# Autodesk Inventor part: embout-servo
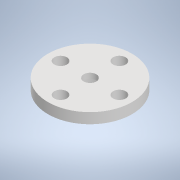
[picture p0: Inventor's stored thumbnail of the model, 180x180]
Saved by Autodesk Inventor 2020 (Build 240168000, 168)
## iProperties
Created: 2021-10
Part Number: embout-servo
Material: Générique
Document SubType Name: Modeling
Designer: bruno
Density: 26.3858 g/cm^3
Appearance: Par défaut
Mass: 20 g
Surface Area: 9.31691 cm^2
Volume: 0.757985 cm^3
Author: bruno
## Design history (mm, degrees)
sketch "Esquisse1"
  geometry: L1 (0, 0)-(2.5, 0); L2 (2, -4)-(0.5, -4); L3 (0, -3.5)-(0, -2.5); L4 (2.5, 0)-(5, 0); L5 (5, -1.5)-(5, -10); L6 (5, -10)-(2.5, -10); L7 (2.5, -10)-(2.5, -4.5); L8 (3.75, 0)-(0, 0); L9 (0, -1.5)-(0, -2.5); L10 (0, -2.5)-(3.75, -2.5); L11 (3.75, -2.5)-(3.75, -1.5); L12 (3.75, 0)-(5, 0); L13 (5, -1.5)-(3.75, -1.5); A1 r 0.5 centre (0.5, -3.5) between (0, -3.5) and (0.5, -4); A2 r 0.5 centre (2, -4.5) between (2.5, -4.5) and (2, -4)
  constraints: 26 end point, 6 parallel, 4 horizontal, 4 point on circle, 4 tangent, 2 centre point, 2 perpendicular, 2 point on line, 1 equal radius, 1 midpoint
  dimensions: "d0" = 2.5 distance of L5.end L6.end; "d1" = 5 distance between parallel lines of L3 L5; "d2" = 10 distance between parallel lines of L4 L6; "d3" = 4 distance between parallel lines of L1 L2; "d4" = 2.5 distance between parallel lines of L1 L10; "d5" = 0.5 radius of A1; "d11" = 1.5 distance between parallel lines of L12 L13
revolve "Révolution1" sketch "Esquisse1" stored, may be unused: angle "d6" = 90 deg
sketch "Esquisse2"
  geometry: C1 r 1.5 at (0, 7); 1 further point
  constraints: 1 centre point
  dimensions: "d7" = 3 diameter of C1; "d8" = 7 distance of C1.centre point (0, 0)
extrude "Extrusion1" cut sketch "Esquisse2" distance "d9" = 10; taper "d10" = 0 deg
pattern_circular "Réseau circulaire1" dims angle "d13" = 360 deg
node "Solide1"
